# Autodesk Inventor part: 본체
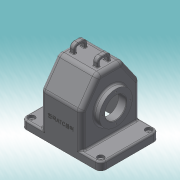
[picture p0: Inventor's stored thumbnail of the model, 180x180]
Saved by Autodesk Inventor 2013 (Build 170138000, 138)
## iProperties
Created: 2016-12
Part Number: 본체
Material: 일반
Document SubType Name: Modeling
Designer: dgall
Density: 1 g/cm^3
Author: dgall
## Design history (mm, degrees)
sketch "스케치1"
  geometry: L1 (-75, 55)-(75, 55); L2 (75, 55)-(75, -55); L3 (75, -55)-(-75, -55); L4 (-75, -55)-(-75, 55); 3 further points
  constraints: 8 end point, 2 midpoint, 2 parallel, 1 horizontal, 1 horizontal alignment, 1 perpendicular, 1 vertical alignment
  dimensions: "d0" = 150 distance of L1.start L1.end; "d2" = 110 distance of L1.end L2.end
extrude "돌출1" new body sketch "스케치1" distance "d3" = 15; taper "d4" = 0 deg
sketch "스케치2"
  geometry: L1 (55, 15)-(-55, 15) reference; L2 (-55, 15)-(-55, 80); L3 (-55, 80)-(-23.491, 125); L4 (-23.491, 125)-(23.491, 125); L5 (23.491, 125)-(55, 80); L6 (55, 80)-(55, 15); L7 (-55, 0)-(55, 0) reference; 3 further points
  constraints: 10 end point, 2 midpoint, 2 perpendicular, 1 horizontal alignment, 1 parallel, 1 vertical alignment
  dimensions: "d5" = 35 deg angle of L2 L3; "d6" = 80 distance from line of L2.end L7; "d7" = 125 distance between parallel lines of L4 L7
extrude "돌출2" join sketch "스케치2" stored distance "d8" = 77; taper "d9" = 0 deg
sketch "스케치3"
  geometry: L1 (-55, 80)-(-23.491, 125) reference; L2 (-23.491, 125)-(23.491, 125) reference; L3 (23.491, 125)-(55, 80) reference; L4 (55, 80)-(55, 15) reference; L5 (-55, 15)-(-55, 80) reference; L6 (-55, 0)-(-55, 15) reference; L7 (55, 0)-(55, 15) reference; L8 (-55, 0)-(55, 0) reference; L9 (20.888, 120)-(-20.888, 120); L10 (-20.888, 120)-(-50, 78.424); L11 (50, 78.424)-(20.888, 120); L12 (-50, 78.424)-(-50, 0); L13 (50, 78.424)-(50, 0); 1 further point
  constraints: 10 end point, 2 perpendicular, 2 point on line, 1 other
  dimensions: "d10" = 5 distance between parallel lines of L3 L11; "d11" = 5 distance between parallel lines of L1 L10; "d12" = 5 distance between parallel lines of L5 L12; "d13" = 5 distance between parallel lines of L4 L13
extrude "돌출3" cut sketch "스케치3" stored distance "d14" = 67; taper "d15" = 0 deg
sketch "스케치4"
  geometry: L1 (-38.5, 80)-(-38.5, 15) reference; L2 (-38.5, 125)-(-38.5, 80) reference; L3 (-43.5, 65)-(-19.5, 65); L4 (-43.5, 65)-(-43.5, 102.5); L5 (-43.5, 102.5)-(-38.5, 102.5); L6 (33.5, 78.424)-(-33.5, 78.424) reference; L7 (33.5, 78.424)-(33.5, 120) reference; L8 (33.5, 120)-(-33.5, 120) reference; L9 (-33.5, 120)-(-33.5, 78.424) reference; L10 (-33.5, 78.424)-(-33.5, 0) reference; L11 (-33.5, 106)-(-19.5, 92); L12 (-19.5, 92)-(-19.5, 65); L13 (-38.5, 102.5)-(-38.5, 106); L14 (-33.5, 106)-(-38.5, 106); 1 further point
  constraints: 14 end point, 4 perpendicular, 2 point on line, 1 midpoint, 1 parallel
  dimensions: "d17" = 65 distance from line of point (0, 0) L3; "d18" = 75 diameter of L5 L3; "d19" = 5 distance of L4.end L5.end; "d20" = 54 diameter of L11.end L3; "d21" = 24 distance of L3.start L3.end; "d22" = 45 deg angle of L12 L11
revolve "회전1" sketch "스케치4" stored, may be unused: angle "d23" = 90 deg
sketch "스케치5"
  geometry: L1 (-43.5, 27.5)-(-43.5, 102.5) reference; L2 (-19.5, 38)-(-19.5, 92) reference; L3 (-19.5, 65)-(-43.5, 65); L4 (-43.5, 85)-(-19.5, 85); L5 (-19.5, 65)-(-19.5, 85); L6 (-43.5, 65)-(-43.5, 85); 1 further point
  constraints: 8 end point, 2 collinear, 2 midpoint, 2 point on line, 1 perpendicular
  dimensions: "d24" = 40 diameter of L4 L3
revolve "회전2" sketch "스케치5" stored, may be unused: angle "d25" = 90 deg
sketch "스케치7"
  geometry: L1 (0, -55)-(0, 55) reference; C1 r 31 at (65, 0); 2 further points
  constraints: 1 centre point, 1 horizontal alignment, 1 midpoint
  dimensions: "d29" = 62 diameter of C1; "d31" = 65 distance from line of C1.centre L1
extrude "돌출4" join sketch "스케치7" distance "d32" = 10; taper "d33" = 0 deg
sketch "스케치9"
  geometry: C1 r 31 at (0, 0) reference; C2 r 20 at (0, 0); 1 further point
  constraints: 1 centre point, 1 coincident
  dimensions: "d34" = 40 diameter of C2
extrude "돌출5" cut sketch "스케치9" stored distance "d36" = 10; taper "d37" = 0 deg
sketch "스케치10"
  geometry: C1 r 20 at (0, 0) reference; 2 further points
  constraints: 1 horizontal alignment
  dimensions: "d38" = 29 distance of C1.centre point (-29, 0)
hole "구멍1" sketch "스케치10" at (-29, 0) diameter "d39" = 2.621; stored, may be unused: countersink angle "d43" = 90 deg, drill point angle "d45" = 118 deg; dims "d40" = 6, "d41" = 4, "d42" = 2, "d44" = 8
sketch "스케치11"
  geometry: C1 r 20 at (0, 0) reference; 2 further points
  constraints: 1 vertical alignment
  dimensions: "d49" = 26 distance of C1.centre point (0, 26)
hole "구멍2" sketch "스케치11" at (0, 26) diameter "d50" = 2.621; stored, may be unused: countersink angle "d54" = 90 deg, drill point angle "d56" = 118 deg; dims "d51" = 6, "d52" = 4, "d53" = 2, "d55" = 8
node "작업 평면2"
  node "작업 평면1"
sketch "스케치12"
  geometry: L1 (125, 23.491)-(125, -23.491) reference; L2 (125, 12.5)-(140, 12.5); L3 (140, 12.5)-(140, -12.5); L4 (140, -12.5)-(125, -12.5); L5 (125, 7.5)-(135, 7.5); L6 (135, 7.5)-(135, -7.5); L7 (135, -7.5)-(125, -7.5); L8 (0, -50)-(0, 50) reference; 3 further points
  constraints: 12 end point, 5 perpendicular, 4 point on line, 2 horizontal alignment, 2 midpoint, 1 parallel
  dimensions: "d61" = 25 distance of L2.end L3.end; "d63" = 15 distance of L5.end L6.end; "d64" = 140 distance between parallel lines of L3 L8; "d65" = 5 distance between parallel lines of L6 L3
extrude "돌출6" join sketch "스케치12" distance "d66" = 8; taper "d67" = 0 deg
fillet "모깎기1" dims "d68" = 10
sketch "스케치14"
  geometry: L1 (75, -45)-(75, 45) reference; L2 (65, 55)-(38.5, 55) reference; L3 (38.5, 55)-(38.5, -55) reference; L4 (38.5, -55)-(65, -55) reference; A1 r 10 centre (-65, -45) between (-75, -45) and (-65, -55) reference; A2 r 10 centre (-65, 45) between (-65, 55) and (-75, 45) reference; A3 r 10 centre (65, -45) between (65, -55) and (75, -45) reference; A4 r 10 centre (65, 45) between (75, 45) and (65, 55) reference; 5 further points
  constraints: 4 coincident
hole "구멍3" sketch "스케치14" at (65, -45), (65, 45), (-65, 45), (-65, -45) diameter "d69" = 5; stored, may be unused: countersink angle "d73" = 90 deg, drill point angle "d75" = 118 deg; dims "d70" = 6, "d71" = 12, "d72" = 5, "d74" = 8
fillet "모깎기2" dims "d76" = 8
fillet "모깎기3" dims "d77" = 3
fillet "모깎기4" dims "d78" = 1
fillet "모깎기5" dims "d79" = 1
fillet "모깎기6" dims "d80" = 10
fillet "모깎기7" dims "d81" = 8
fillet "모깎기8" dims "d82" = 3
sketch "스케치15"
  geometry: L1 (0, 0)-(130, 0) reference; L2 (103.5, -76.847)-(103.5, -18) reference; 2 further points
  constraints: 1 other
  dimensions: "d83" = 38.5 distance from line of point (65, -45) L2; "d84" = 45 distance from line of L1 point (65, -45)
feature "엠보싱1" sketch "스케치15" dims "d0" = 150, "d2" = 110, "d85" = 0.5, "d86" = 0
fillet "모깎기9" dims "d87" = 3
fillet "모깎기10" dims "d88" = 3
fillet "모깎기11" dims "d89" = 3
chamfer "모따기1" distance "d90" = 1; stored, may be unused: second distance "d91" = 2, angle "d92" = 45 deg
node "솔리드1"
pattern_circular "원형 패턴1" dims angle "d47" = 360 deg
pattern_circular "원형 패턴2" dims angle "d58" = 360 deg
mirror "대칭1"
node "투영된 루프1"
node "투영된 루프2"
other parameters: "d60" = 18
